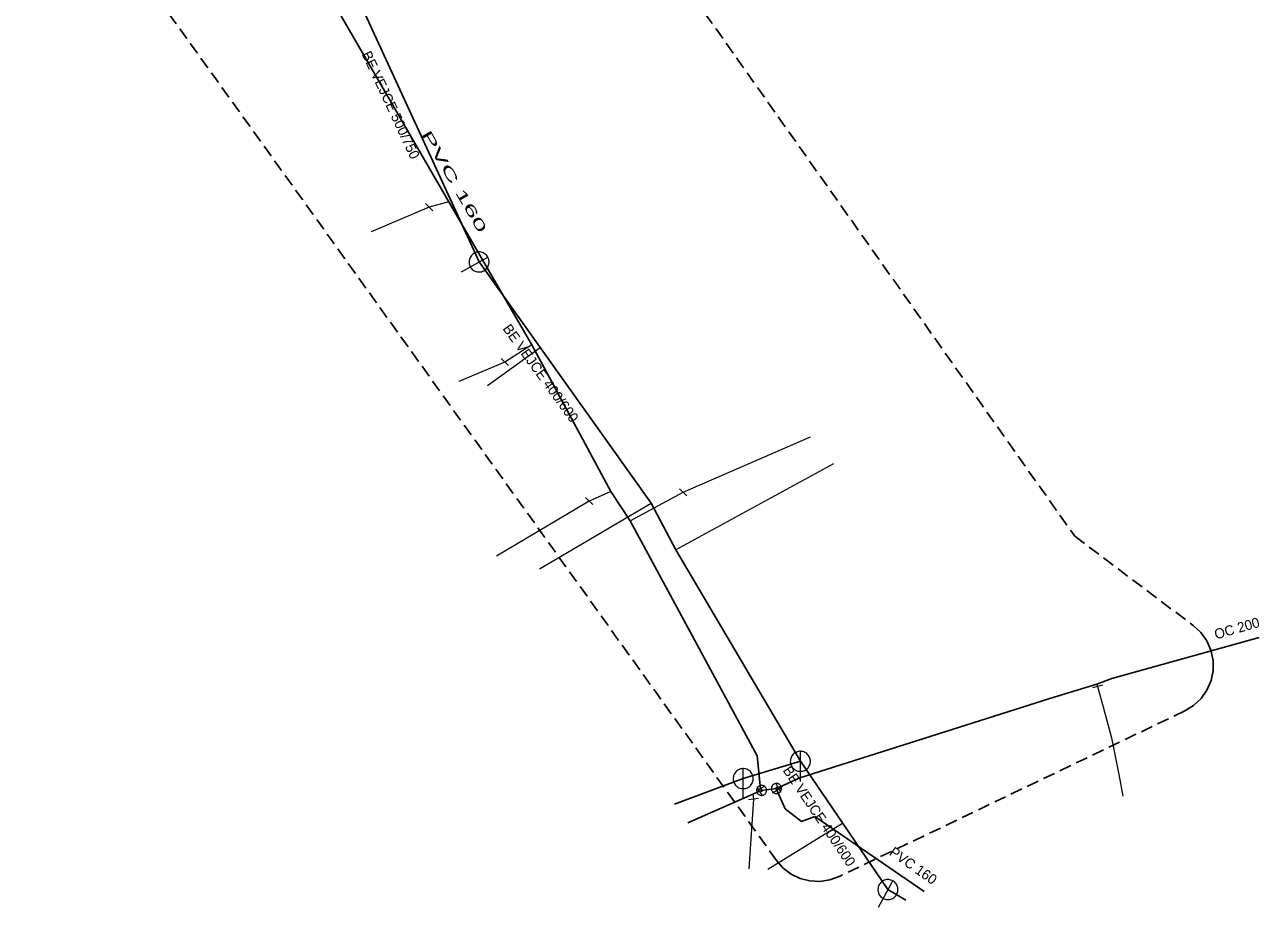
# Model space of a CAD drawing. Extents: x -749365 to -748625, y -965388 to -964881.
# Drawn here: x -748747.8 to -748624.8, y -965387.7 to -965299.8 of the extents above; entities that cross this region are included whole.
import ezdxf

# ---------------------------------------------------------------- set-up
doc = ezdxf.new("R2010")
doc.units = 0
doc.header["$LTSCALE"] = 0.4
doc.linetypes.add('MEDIUM_DASHED', pattern=[4.5, 3, -1.5])
for name, color, linetype, lineweight in [('1', 7, 'MEDIUM_DASHED', 25), ('11', 7, 'Continuous', 13), ('13', 7, 'Continuous', 13), ('14', 7, 'Continuous', 13), ('17', 7, 'Continuous', 25), ('22', 7, 'Continuous', 13), ('34', 7, 'Continuous', 13), ('47', 7, 'Continuous', 13)]:
    doc.layers.add(name, color=color, linetype=linetype, lineweight=lineweight)

msp = doc.modelspace()

# ---------------------------------------------------------------- linework, layer by layer
at = {"layer": '1'}
msp.add_lwpolyline([(-748720.498, -965241.345), (-748643.194, -965350.737), (-748631.381, -965359.639), (-748630.631, -965360.335), (-748630.039, -965361.169), (-748629.629, -965362.105), (-748629.418, -965363.106), (-748629.415, -965364.128), (-748629.619, -965365.13), (-748630.024, -965366.069), (-748630.611, -965366.907), (-748631.356, -965367.607), (-748632.228, -965368.141), (-748666.656, -965384.649), (-748667.592, -965384.988), (-748668.577, -965385.135), (-748669.571, -965385.084), (-748670.535, -965384.837), (-748671.431, -965384.404), (-748672.224, -965383.802), (-748672.881, -965383.055), (-748747.771, -965278.626)], dxfattribs=at)
at = {"layer": '11'}
for p, q in [((-748701.673, -965335.736), (-748696.448, -965331.919)), ((-748667.23, -965343.523), (-748682.924, -965352.095)), ((-748696.508, -965353.976), (-748685.38, -965347.431)), ((-748673.774, -965383.912), (-748666.309, -965379.337))]:
    msp.add_line(p, q, dxfattribs=at)
at = {"layer": '13'}
for p, q in [((-748707.495, -965317.95), (-748713.272, -965320.399)), ((-748705.515, -965317.423), (-748707.495, -965317.95)), ((-748697.278, -965331.659), (-748699.958, -965333.389)), ((-748699.958, -965333.389), (-748704.545, -965335.317)), ((-748682.19, -965346.361), (-748669.522, -965340.844)), ((-748691.546, -965347.242), (-748700.777, -965352.736)), ((-748689.392, -965346.28), (-748691.546, -965347.242)), ((-748687.454, -965349.21), (-748682.19, -965346.361)), ((-748675.182, -965376.943), (-748675.645, -965383.888))]:
    msp.add_line(p, q, dxfattribs=at)
msp.add_lwpolyline([(-748640.925, -965365.715), (-748640.37, -965367.75), (-748639.53, -965370.829), (-748638.809, -965374.489), (-748638.386, -965376.639)], dxfattribs=at)
at = {"layer": '14', "lineweight": 25}
for p, q in [((-748715.64, -965294.859), (-748702.52, -965323.41)), ((-748676.21, -965374.89), (-748670.52, -965373.17)), ((-748670.52, -965373.17), (-748661.794, -965385.951)), ((-748683.06, -965377.441), (-748676.21, -965374.89)), ((-748661.794, -965385.951), (-748660.026, -965387.015))]:
    msp.add_line(p, q, dxfattribs=at)
at = {"layer": '14'}
for p, q in [((-748640.989, -965365.48), (-748640.925, -965365.715)), ((-748675.267, -965376.429), (-748675.182, -965376.943)), ((-748674.38, -965376.063), (-748674.574, -965376.143)), ((-748674.485, -965375.898), (-748674.38, -965376.063)), ((-748672.906, -965375.871), (-748672.715, -965375.805)), ((-748672.906, -965375.871), (-748672.863, -965376.057))]:
    msp.add_line(p, q, dxfattribs=at)
at = {"layer": '14', "lineweight": 25}
msp.add_lwpolyline([(-748702.52, -965323.41), (-748685.379, -965347.431), (-748682.923, -965352.094), (-748670.52, -965373.17)], dxfattribs=at)
at = {"layer": '17'}
msp.add_line((-748674.38, -965376.063), (-748672.906, -965375.871), dxfattribs=at)
for points in [[(-748738.234, -965270.822), (-748726.585, -965284.577), (-748724.84, -965286.638), (-748719.677, -965293.835), (-748717.51, -965296.688), (-748705.515, -965317.423), (-748697.278, -965331.659), (-748689.392, -965346.28), (-748687.454, -965349.21), (-748674.822, -965372.635), (-748674.485, -965375.898)], [(-748624.819, -965360.817), (-748639.489, -965364.93), (-748640.989, -965365.48), (-748645.67, -965366.92), (-748670.677, -965374.831), (-748672.715, -965375.805)], [(-748674.574, -965376.143), (-748675.267, -965376.429), (-748681.724, -965379.304)], [(-748672.863, -965376.057), (-748672.02, -965377.897), (-748670.403, -965379.153), (-748669.061, -965378.656), (-748658.202, -965386.141)]]:
    msp.add_lwpolyline(points, dxfattribs=at)
at = {"layer": '22'}
for p, q in [((-748704.264, -965324.388), (-748701.648, -965322.92)), ((-748670.52, -965375.17), (-748670.519, -965372.17)), ((-748676.21, -965376.89), (-748676.209, -965373.89)), ((-748662.733, -965387.717), (-748661.324, -965385.068))]:
    msp.add_line(p, q, dxfattribs=at)
for points in [[(-748702.031, -965324.282), (-748701.939, -965324.223), (-748701.853, -965324.155), (-748701.775, -965324.077), (-748701.707, -965323.992), (-748701.648, -965323.9), (-748701.6, -965323.802), (-748701.562, -965323.698), (-748701.537, -965323.592), (-748701.523, -965323.483), (-748701.521, -965323.374), (-748701.53, -965323.265), (-748701.553, -965323.157), (-748701.586, -965323.053), (-748701.631, -965322.953), (-748701.686, -965322.858), (-748701.751, -965322.771), (-748701.825, -965322.69), (-748701.908, -965322.618), (-748701.999, -965322.557), (-748702.094, -965322.505), (-748702.197, -965322.464), (-748702.301, -965322.434), (-748702.41, -965322.416), (-748702.519, -965322.41), (-748702.628, -965322.416), (-748702.736, -965322.434), (-748702.842, -965322.463), (-748702.943, -965322.504), (-748703.04, -965322.556), (-748703.13, -965322.618), (-748703.213, -965322.689), (-748703.287, -965322.769), (-748703.353, -965322.857), (-748703.409, -965322.951), (-748703.453, -965323.052), (-748703.487, -965323.155), (-748703.509, -965323.263), (-748703.519, -965323.372), (-748703.518, -965323.481), (-748703.503, -965323.59), (-748703.478, -965323.696), (-748703.441, -965323.799), (-748703.393, -965323.898), (-748703.334, -965323.99), (-748703.265, -965324.076), (-748703.189, -965324.153), (-748703.103, -965324.222), (-748703.01, -965324.281), (-748702.912, -965324.329), (-748702.81, -965324.367), (-748702.703, -965324.393), (-748702.595, -965324.407), (-748702.485, -965324.41), (-748702.377, -965324.399), (-748702.269, -965324.378), (-748702.164, -965324.344), (-748702.064, -965324.3)], [(-748669.52, -965373.17), (-748669.525, -965373.061), (-748669.543, -965372.953), (-748669.573, -965372.847), (-748669.613, -965372.746), (-748669.665, -965372.649), (-748669.727, -965372.559), (-748669.799, -965372.476), (-748669.879, -965372.402), (-748669.967, -965372.336), (-748670.061, -965372.281), (-748670.161, -965372.236), (-748670.266, -965372.203), (-748670.373, -965372.181), (-748670.482, -965372.171), (-748670.592, -965372.173), (-748670.7, -965372.187), (-748670.807, -965372.212), (-748670.91, -965372.249), (-748671.008, -965372.298), (-748671.1, -965372.356), (-748671.186, -965372.425), (-748671.263, -965372.502), (-748671.332, -965372.588), (-748671.391, -965372.68), (-748671.439, -965372.778), (-748671.476, -965372.881), (-748671.502, -965372.988), (-748671.516, -965373.096), (-748671.519, -965373.206), (-748671.509, -965373.315), (-748671.488, -965373.422), (-748671.454, -965373.526), (-748671.41, -965373.626), (-748671.355, -965373.721), (-748671.289, -965373.809), (-748671.215, -965373.889), (-748671.132, -965373.961), (-748671.042, -965374.023), (-748670.946, -965374.075), (-748670.844, -965374.116), (-748670.739, -965374.146), (-748670.631, -965374.164), (-748670.521, -965374.17), (-748670.412, -965374.164), (-748670.304, -965374.146), (-748670.199, -965374.117), (-748670.097, -965374.076), (-748670, -965374.024), (-748669.91, -965373.962), (-748669.827, -965373.891), (-748669.752, -965373.811), (-748669.687, -965373.723), (-748669.631, -965373.629), (-748669.587, -965373.529), (-748669.553, -965373.425), (-748669.531, -965373.317), (-748669.521, -965373.208)], [(-748675.21, -965374.89), (-748675.215, -965374.781), (-748675.233, -965374.673), (-748675.263, -965374.567), (-748675.303, -965374.466), (-748675.355, -965374.369), (-748675.417, -965374.279), (-748675.489, -965374.196), (-748675.569, -965374.122), (-748675.657, -965374.056), (-748675.751, -965374.001), (-748675.851, -965373.956), (-748675.956, -965373.923), (-748676.063, -965373.901), (-748676.172, -965373.891), (-748676.282, -965373.893), (-748676.39, -965373.907), (-748676.497, -965373.932), (-748676.6, -965373.969), (-748676.698, -965374.018), (-748676.79, -965374.076), (-748676.876, -965374.145), (-748676.953, -965374.222), (-748677.022, -965374.308), (-748677.081, -965374.4), (-748677.129, -965374.498), (-748677.166, -965374.601), (-748677.192, -965374.708), (-748677.206, -965374.816), (-748677.209, -965374.926), (-748677.199, -965375.035), (-748677.178, -965375.142), (-748677.144, -965375.246), (-748677.1, -965375.346), (-748677.045, -965375.441), (-748676.979, -965375.529), (-748676.905, -965375.609), (-748676.822, -965375.681), (-748676.732, -965375.743), (-748676.636, -965375.795), (-748676.534, -965375.836), (-748676.429, -965375.866), (-748676.321, -965375.884), (-748676.211, -965375.89), (-748676.102, -965375.884), (-748675.994, -965375.866), (-748675.889, -965375.837), (-748675.787, -965375.796), (-748675.69, -965375.744), (-748675.6, -965375.682), (-748675.517, -965375.611), (-748675.442, -965375.531), (-748675.377, -965375.443), (-748675.321, -965375.349), (-748675.277, -965375.249), (-748675.243, -965375.145), (-748675.221, -965375.037), (-748675.211, -965374.928)], [(-748660.911, -965386.421), (-748660.865, -965386.322), (-748660.83, -965386.218), (-748660.807, -965386.11), (-748660.795, -965386.002), (-748660.795, -965385.892), (-748660.808, -965385.783), (-748660.832, -965385.676), (-748660.868, -965385.573), (-748660.915, -965385.474), (-748660.972, -965385.381), (-748661.039, -965385.294), (-748661.116, -965385.216), (-748661.2, -965385.146), (-748661.292, -965385.086), (-748661.39, -965385.036), (-748661.492, -965384.998), (-748661.598, -965384.97), (-748661.706, -965384.954), (-748661.816, -965384.951), (-748661.924, -965384.959), (-748662.033, -965384.98), (-748662.137, -965385.012), (-748662.238, -965385.055), (-748662.333, -965385.109), (-748662.422, -965385.173), (-748662.503, -965385.246), (-748662.576, -965385.329), (-748662.639, -965385.417), (-748662.693, -965385.514), (-748662.735, -965385.614), (-748662.767, -965385.719), (-748662.786, -965385.827), (-748662.794, -965385.936), (-748662.79, -965386.045), (-748662.773, -965386.154), (-748662.745, -965386.259), (-748662.706, -965386.362), (-748662.655, -965386.459), (-748662.595, -965386.55), (-748662.524, -965386.634), (-748662.445, -965386.71), (-748662.359, -965386.776), (-748662.264, -965386.833), (-748662.165, -965386.879), (-748662.061, -965386.914), (-748661.955, -965386.938), (-748661.846, -965386.949), (-748661.736, -965386.949), (-748661.627, -965386.937), (-748661.521, -965386.913), (-748661.417, -965386.878), (-748661.318, -965386.83), (-748661.224, -965386.774), (-748661.139, -965386.706), (-748661.06, -965386.63), (-748660.99, -965386.545), (-748660.93, -965386.454)]]:
    msp.add_lwpolyline(points, close=True, dxfattribs=at)
at = {"layer": '34'}
for p, q in [((-748707.852, -965317.6), (-748707.138, -965318.3)), ((-748700.315, -965333.039), (-748699.601, -965333.739)), ((-748682.547, -965346.011), (-748681.833, -965346.711)), ((-748691.903, -965346.892), (-748691.189, -965347.592)), ((-748640.442, -965365.582), (-748641.407, -965365.846)), ((-748674.045, -965375.66), (-748674.925, -965376.134)), ((-748674.336, -965376.582), (-748674.81, -965375.702)), ((-748672.952, -965375.365), (-748672.478, -965376.245)), ((-748674.688, -965376.861), (-748675.675, -965377.023)), ((-748673.302, -965376.294), (-748672.422, -965375.82))]:
    msp.add_line(p, q, dxfattribs=at)
at = {"layer": '47'}
for points in [[(-748673.926, -965375.851), (-748673.951, -965375.805), (-748673.98, -965375.761), (-748674.014, -965375.722), (-748674.051, -965375.685), (-748674.093, -965375.653), (-748674.138, -965375.625), (-748674.185, -965375.603), (-748674.234, -965375.585), (-748674.284, -965375.572), (-748674.336, -965375.564), (-748674.389, -965375.563), (-748674.441, -965375.567), (-748674.492, -965375.575), (-748674.543, -965375.59), (-748674.591, -965375.609), (-748674.637, -965375.634), (-748674.681, -965375.663), (-748674.721, -965375.698), (-748674.757, -965375.734), (-748674.789, -965375.776), (-748674.817, -965375.821), (-748674.84, -965375.868), (-748674.858, -965375.917), (-748674.871, -965375.967), (-748674.878, -965376.019), (-748674.879, -965376.072), (-748674.876, -965376.124), (-748674.867, -965376.175), (-748674.852, -965376.226), (-748674.833, -965376.274), (-748674.808, -965376.32), (-748674.779, -965376.364), (-748674.745, -965376.404), (-748674.708, -965376.44), (-748674.666, -965376.472), (-748674.622, -965376.5), (-748674.575, -965376.523), (-748674.526, -965376.541), (-748674.475, -965376.554), (-748674.423, -965376.561), (-748674.37, -965376.562), (-748674.319, -965376.559), (-748674.267, -965376.55), (-748674.216, -965376.535), (-748674.168, -965376.516), (-748674.122, -965376.491), (-748674.078, -965376.462), (-748674.039, -965376.429), (-748674.002, -965376.391), (-748673.97, -965376.349), (-748673.942, -965376.305), (-748673.92, -965376.258), (-748673.902, -965376.209), (-748673.889, -965376.158), (-748673.881, -965376.106), (-748673.88, -965376.053), (-748673.884, -965376.002), (-748673.892, -965375.95), (-748673.907, -965375.899)], [(-748672.452, -965375.659), (-748672.477, -965375.613), (-748672.506, -965375.569), (-748672.54, -965375.53), (-748672.577, -965375.493), (-748672.619, -965375.461), (-748672.664, -965375.433), (-748672.711, -965375.411), (-748672.76, -965375.393), (-748672.81, -965375.38), (-748672.862, -965375.372), (-748672.915, -965375.371), (-748672.967, -965375.375), (-748673.018, -965375.383), (-748673.069, -965375.398), (-748673.117, -965375.417), (-748673.163, -965375.442), (-748673.207, -965375.471), (-748673.247, -965375.506), (-748673.283, -965375.542), (-748673.315, -965375.584), (-748673.343, -965375.629), (-748673.366, -965375.676), (-748673.384, -965375.725), (-748673.397, -965375.775), (-748673.404, -965375.827), (-748673.405, -965375.88), (-748673.402, -965375.932), (-748673.393, -965375.983), (-748673.378, -965376.034), (-748673.359, -965376.082), (-748673.334, -965376.128), (-748673.305, -965376.172), (-748673.271, -965376.212), (-748673.234, -965376.248), (-748673.192, -965376.28), (-748673.148, -965376.308), (-748673.101, -965376.331), (-748673.052, -965376.349), (-748673.001, -965376.362), (-748672.949, -965376.369), (-748672.896, -965376.37), (-748672.845, -965376.367), (-748672.793, -965376.358), (-748672.742, -965376.343), (-748672.694, -965376.324), (-748672.648, -965376.299), (-748672.604, -965376.27), (-748672.565, -965376.237), (-748672.528, -965376.199), (-748672.496, -965376.157), (-748672.468, -965376.113), (-748672.446, -965376.066), (-748672.428, -965376.017), (-748672.415, -965375.966), (-748672.407, -965375.914), (-748672.406, -965375.861), (-748672.41, -965375.81), (-748672.418, -965375.758), (-748672.433, -965375.707)], [(-748672.831, -965375.836), (-748672.835, -965375.828), (-748672.84, -965375.821), (-748672.845, -965375.815), (-748672.851, -965375.809), (-748672.858, -965375.803), (-748672.866, -965375.799), (-748672.873, -965375.795), (-748672.881, -965375.792), (-748672.89, -965375.79), (-748672.898, -965375.789), (-748672.907, -965375.789), (-748672.916, -965375.789), (-748672.924, -965375.791), (-748672.932, -965375.792), (-748672.94, -965375.796), (-748672.948, -965375.8), (-748672.955, -965375.805), (-748672.961, -965375.81), (-748672.967, -965375.816), (-748672.973, -965375.823), (-748672.977, -965375.831), (-748672.981, -965375.838), (-748672.984, -965375.846), (-748672.987, -965375.855), (-748672.987, -965375.863), (-748672.987, -965375.872), (-748672.987, -965375.881), (-748672.985, -965375.889), (-748672.984, -965375.897), (-748672.98, -965375.905), (-748672.976, -965375.913), (-748672.971, -965375.92), (-748672.966, -965375.926), (-748672.96, -965375.932), (-748672.953, -965375.938), (-748672.946, -965375.942), (-748672.938, -965375.946), (-748672.93, -965375.949), (-748672.921, -965375.952), (-748672.913, -965375.952), (-748672.904, -965375.952), (-748672.895, -965375.952), (-748672.887, -965375.95), (-748672.879, -965375.949), (-748672.871, -965375.945), (-748672.863, -965375.941), (-748672.856, -965375.936), (-748672.85, -965375.931), (-748672.844, -965375.925), (-748672.838, -965375.918), (-748672.834, -965375.911), (-748672.83, -965375.903), (-748672.827, -965375.895), (-748672.825, -965375.886), (-748672.824, -965375.878), (-748672.824, -965375.869), (-748672.824, -965375.86), (-748672.826, -965375.852), (-748672.827, -965375.844)], [(-748674.305, -965376.028), (-748674.309, -965376.02), (-748674.314, -965376.013), (-748674.319, -965376.007), (-748674.325, -965376.001), (-748674.332, -965375.995), (-748674.34, -965375.991), (-748674.347, -965375.987), (-748674.355, -965375.984), (-748674.364, -965375.982), (-748674.372, -965375.981), (-748674.381, -965375.981), (-748674.39, -965375.981), (-748674.398, -965375.983), (-748674.406, -965375.984), (-748674.414, -965375.988), (-748674.422, -965375.992), (-748674.429, -965375.997), (-748674.435, -965376.002), (-748674.441, -965376.008), (-748674.447, -965376.015), (-748674.451, -965376.023), (-748674.455, -965376.03), (-748674.458, -965376.038), (-748674.461, -965376.047), (-748674.461, -965376.055), (-748674.461, -965376.064), (-748674.461, -965376.073), (-748674.459, -965376.081), (-748674.458, -965376.089), (-748674.454, -965376.097), (-748674.45, -965376.105), (-748674.445, -965376.112), (-748674.44, -965376.118), (-748674.434, -965376.124), (-748674.427, -965376.13), (-748674.42, -965376.134), (-748674.412, -965376.138), (-748674.404, -965376.141), (-748674.395, -965376.144), (-748674.387, -965376.144), (-748674.378, -965376.144), (-748674.369, -965376.144), (-748674.361, -965376.142), (-748674.353, -965376.141), (-748674.345, -965376.137), (-748674.337, -965376.133), (-748674.33, -965376.128), (-748674.324, -965376.123), (-748674.318, -965376.117), (-748674.312, -965376.11), (-748674.308, -965376.103), (-748674.304, -965376.095), (-748674.301, -965376.087), (-748674.299, -965376.078), (-748674.298, -965376.07), (-748674.298, -965376.061), (-748674.298, -965376.052), (-748674.3, -965376.044), (-748674.301, -965376.036)]]:
    msp.add_lwpolyline(points, close=True, dxfattribs=at)

# ---------------------------------------------------------------- texts
at = {"layer": '1'}
for s, rotation, p in [('BE VEJCE 500/750', 295, (-748714.223, -965302.694)), ('BE VEJCE 400/600', 306, (-748700.212, -965330.061)), ('OC 200', 16, (-748629.121, -965361.026)), ('BE VEJCE 400/600', 304, (-748672.307, -965374.072)), ('PVC 160 ', 325, (-748661.747, -965382.44))]:
    msp.add_text(s, height=1, rotation=rotation, dxfattribs=at).set_placement(p)
at = {"layer": '1', "width": 2.15}
msp.add_text('PVC 160 ', height=1, rotation=300, dxfattribs=at).set_placement((-748708.293, -965310.649))

doc.saveas('drawing.dxf')
